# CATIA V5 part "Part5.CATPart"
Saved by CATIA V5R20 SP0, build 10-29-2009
Part number: Part5
Bounding box of the stored display mesh (mm): x 0 to 2, y -5 to 5, z -5 to 5
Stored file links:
  C:\Users\YS\Desktop\독수리\Part5.CATPart
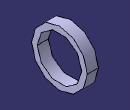
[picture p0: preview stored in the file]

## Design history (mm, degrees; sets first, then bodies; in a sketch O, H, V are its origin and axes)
Body1 (main body)
  Sketch1 on yz-plane, origin (0, 0, 0), H (0, 1, 0), V (0, 0, 1)
    circle A1 centre (0, 0) radius 4
    circle A2 centre (0, 0) radius 5
    radius A1 = 4
    radius A2 = 5
  Pad1: profile Sketch1, direction (1, 0, 0), length 2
